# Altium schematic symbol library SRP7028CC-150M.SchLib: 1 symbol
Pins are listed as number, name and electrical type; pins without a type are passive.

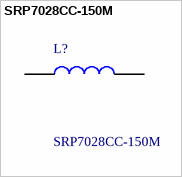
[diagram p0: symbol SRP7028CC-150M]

## SRP7028CC-150M
designator L?
Ind,7.3x6.6x2.8mm,15uH+/-20%,3A,shd; Manufacturer_Name: Bourns; Geometry.Height: 3mm
footprint INDPM7366X300N
pins: 1, 2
